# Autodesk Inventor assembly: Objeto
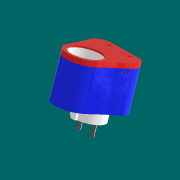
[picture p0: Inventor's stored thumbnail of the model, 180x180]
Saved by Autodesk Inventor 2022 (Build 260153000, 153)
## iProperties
Created: 2021-11
Part Number: Objeto
Document SubType Name: Assembly
Designer: santi
Author: santi
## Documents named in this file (8)
- C:\Users\santi\Documents\Inventor\Carcasa\Objeto.iam
- C:\Users\santi\Documents\Inventor\Carcasa\D1.ipt
- C:\Users\santi\Documents\Inventor\Carcasa\enchufe.ipt
- C:\Users\santi\Documents\Inventor\Carcasa\Fuente.ipt
- C:\Users\santi\Documents\Inventor\Carcasa\RELE.ipt
- C:\Users\santi\Documents\Inventor\Carcasa\Toma.ipt
- C:\Users\santi\Documents\Inventor\Carcasa\cajapt1.ipt
- C:\Users\santi\Documents\Inventor\Carcasa\cajapt2.ipt
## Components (7 placed, 7 different names)
1. D1:1 — Mate:1, Flush:1, Flush:2, Mate:5
2. enchufe:1 — Flush:3, Mate:2, Mate:3, Mate:5, Flush:4, Flush:5, Mate:6, Mate:7
3. Fuente:1 — Flush:3, Mate:2, Flush:5
4. RELE:1 — Mate:1, Flush:1, Flush:2, Flush:4
5. Toma:1 — Mate:3
6. cajapt1:1 — Mate:6, Mate:7, Mate:8, Flush:6
7. cajapt2:1 — Mate:8, Flush:6
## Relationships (13: Mate 7, Flush 6)
- Mate:1: D1:1 ↔ RELE:1
- Flush:1: D1:1 ↔ RELE:1
- Flush:2: D1:1 ↔ RELE:1
- Flush:3: enchufe:1 ↔ Fuente:1
- Mate:2: enchufe:1 ↔ Fuente:1
- Mate:3: enchufe:1 ↔ Toma:1
- Mate:5: D1:1 ↔ enchufe:1
- Flush:4: enchufe:1 ↔ RELE:1
- Flush:5: enchufe:1 ↔ Fuente:1
- Mate:6: enchufe:1 ↔ cajapt1:1
- Mate:7: enchufe:1 ↔ cajapt1:1
- Mate:8: cajapt1:1 ↔ cajapt2:1
- Flush:6: cajapt1:1 ↔ cajapt2:1
